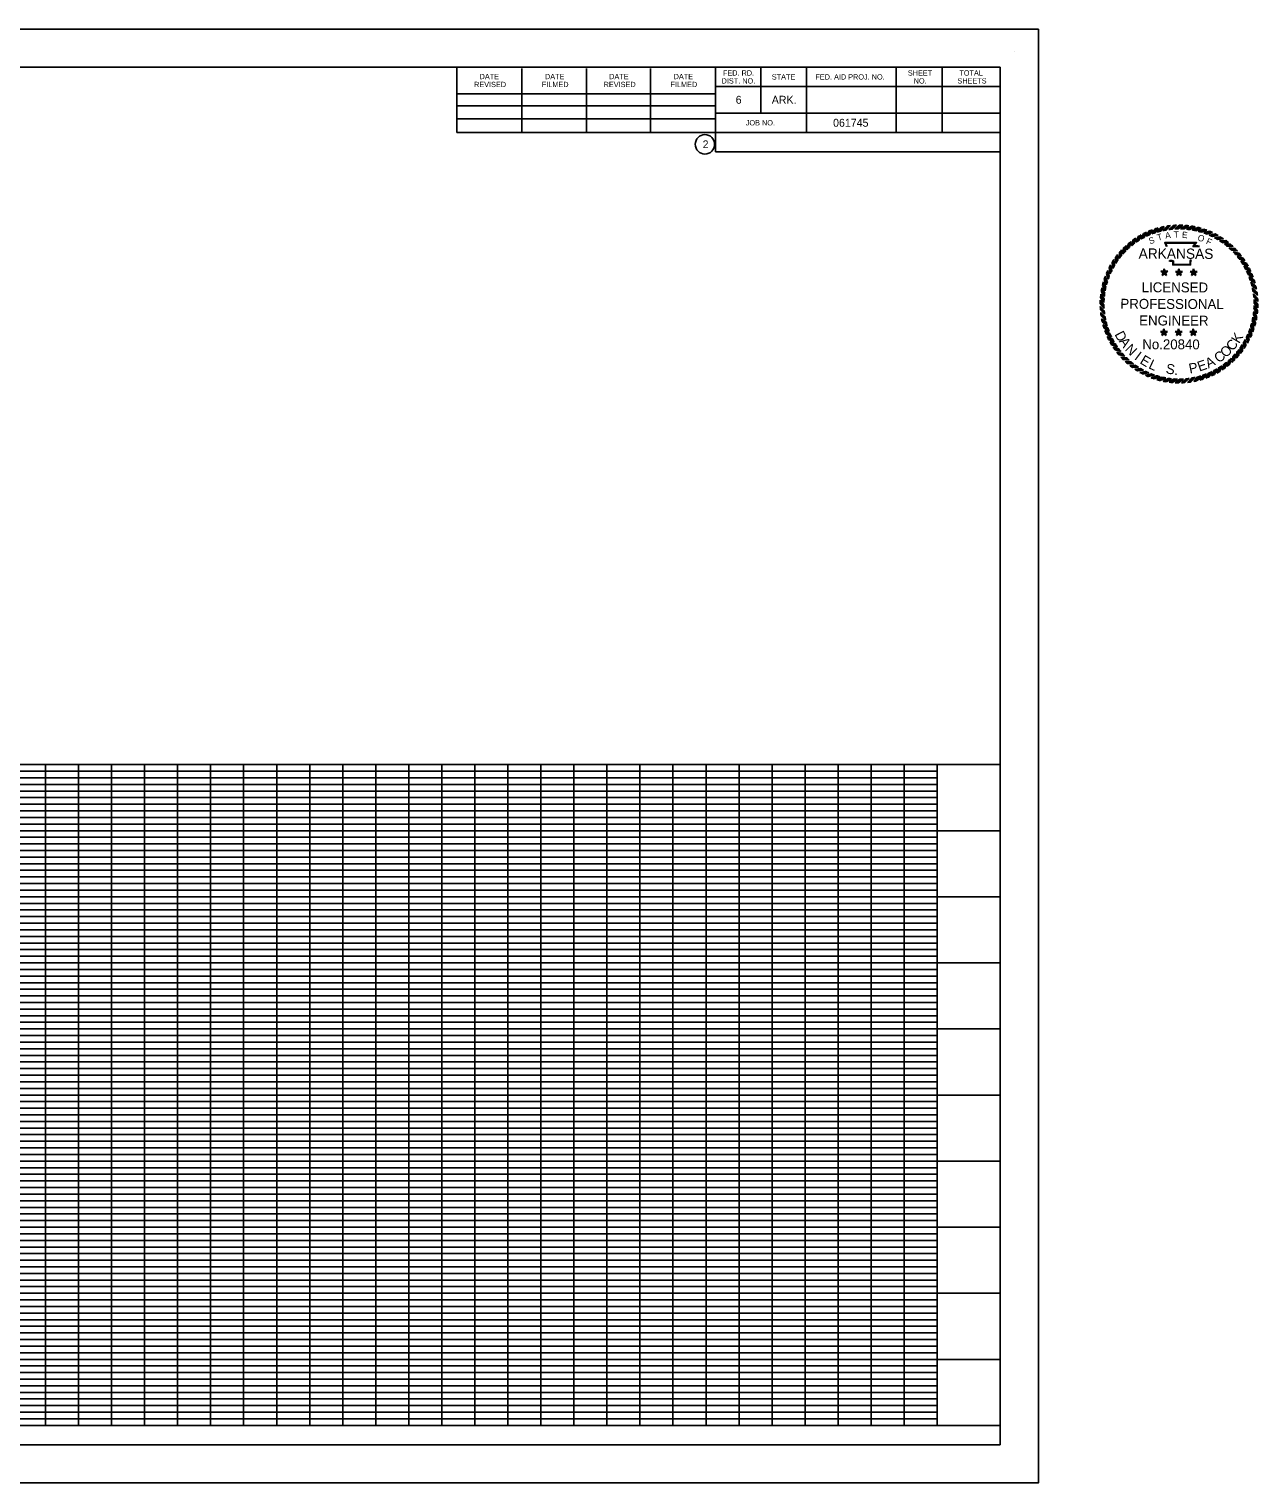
# Model space of a CAD drawing. Extents: x 759422 to 1467355, y 1662254 to 1691786.
# Drawn here: x 1466424 to 1467355, y 1690686 to 1691786 of the extents above; entities that cross this region are included whole.
import ezdxf

# ---------------------------------------------------------------- set-up
doc = ezdxf.new("R2010")
doc.units = 0
doc.layers.add('1', color=7, linetype='Continuous')
doc.layers.add('Default', color=7, linetype='Continuous')

# ---------------------------------------------------------------- blocks, each defined once
blk = doc.blocks.new('STAR')
at = {"layer": 'Default'}
for p, q in [((0.059, 0.019), (-0.059, 0.019)), ((-0.059, 0.019), (0.036, -0.05)), ((0, 0.062), (-0.037, -0.05)), ((-0.036, -0.05), (0.059, 0.019)), ((-0.008, 0), (0.009, 0)), ((0.036, -0.05), (0, 0.062)), ((0, 0.006), (0, -0.008))]:
    blk.add_line(p, q, dxfattribs=at)
blk = doc.blocks.new('RP')
at = {"layer": 'Default'}
for p, q in [((-0.078, 1.266), (0.003, 1.33)), ((-0.058, 1.267), (0.022, 1.33)), ((-0.038, 1.267), (0.04, 1.329)), ((-0.018, 1.268), (0.059, 1.329))]:
    blk.add_line(p, q, dxfattribs=at)
for radius, start, end in [(1.268, 90.7933, 93.5307), (1.33, 87.4562, 89.8699)]:
    blk.add_arc((0, 0), radius, start, end, dxfattribs=at)

msp = doc.modelspace()

# ---------------------------------------------------------------- linework, layer by layer
at = {"layer": '1'}
for p, q in [((1467170.4, 1691768.9), (1467170.4, 1691768.9)), ((1465564.1, 1691757.4), (1467159.4, 1691757.4)), ((1465578.5, 1691757.4), (1466894.6, 1691757.4)), ((1466748.1, 1691708), (1466748.1, 1691757.4)), ((1466797.4, 1691708), (1466797.4, 1691756.4)), ((1466846.2, 1691708), (1466846.2, 1691756.4)), ((1466894.6, 1691708), (1466894.6, 1691756.4)), ((1466943.9, 1691757.4), (1466943.9, 1691693.4)), ((1466978.1, 1691757.4), (1466978.1, 1691722.7)), ((1467012.8, 1691757.4), (1467012.8, 1691708)), ((1467080.7, 1691757.4), (1467080.7, 1691708)), ((1467115.4, 1691757.4), (1467115.4, 1691708)), ((1467159.4, 1690715), (1467159.4, 1691757.4)), ((1466748.1, 1691737.3), (1466943.9, 1691737.3)), ((1467159.4, 1691742.7), (1466943.9, 1691742.7)), ((1467159.4, 1691742.8), (1467159.4, 1691742.8)), ((1466748.1, 1691728), (1466943.9, 1691728)), ((1466748.1, 1691708), (1466748.1, 1691718.3)), ((1466748.1, 1691718.3), (1466943.9, 1691718.3)), ((1467159.4, 1691722.7), (1466943.9, 1691722.7)), ((1466958.7, 1691722.7), (1467159.4, 1691722.7)), ((1467159.4, 1691708), (1466748.1, 1691708)), ((1466943.9, 1691693.4), (1467159.4, 1691693.4)), ((1467159.4, 1691229.7), (1465564.1, 1691229.7)), ((1466436.7, 1690729.7), (1466436.7, 1691229.7)), ((1466461.7, 1690729.7), (1466461.7, 1691229.7)), ((1466486.7, 1690729.7), (1466486.7, 1691229.7)), ((1466511.7, 1690729.7), (1466511.7, 1691229.7)), ((1466536.7, 1690729.7), (1466536.7, 1691229.7)), ((1466561.7, 1690729.7), (1466561.7, 1691229.7)), ((1466586.7, 1690729.7), (1466586.7, 1691229.7)), ((1466611.7, 1690729.7), (1466611.7, 1691229.7)), ((1466636.7, 1690729.7), (1466636.7, 1691229.7)), ((1466661.7, 1690729.7), (1466661.7, 1691229.7)), ((1466686.7, 1690729.7), (1466686.7, 1691229.7)), ((1466711.7, 1690729.7), (1466711.7, 1691229.7)), ((1466736.7, 1690729.7), (1466736.7, 1691229.7)), ((1466761.7, 1690729.7), (1466761.7, 1691229.7)), ((1466786.7, 1690729.7), (1466786.7, 1691229.7)), ((1466811.7, 1690729.7), (1466811.7, 1691229.7)), ((1466836.7, 1690729.7), (1466836.7, 1691229.7)), ((1466861.7, 1690729.7), (1466861.7, 1691229.7)), ((1466886.7, 1690729.7), (1466886.7, 1691229.7)), ((1466911.7, 1690729.7), (1466911.7, 1691229.7)), ((1466936.7, 1690729.7), (1466936.7, 1691229.7)), ((1466961.7, 1690729.7), (1466961.7, 1691229.7)), ((1466986.7, 1690729.7), (1466986.7, 1691229.7)), ((1467011.7, 1690729.7), (1467011.7, 1691229.7)), ((1467036.7, 1690729.7), (1467036.7, 1691229.7)), ((1467061.7, 1690729.7), (1467061.7, 1691229.7)), ((1467086.7, 1690729.7), (1467086.7, 1691229.7)), ((1467111.7, 1690729.7), (1467111.7, 1691229.7)), ((1467111.7, 1691224.7), (1465611.7, 1691224.7)), ((1467111.7, 1691219.7), (1465611.7, 1691219.7)), ((1467111.7, 1691214.7), (1465611.7, 1691214.7)), ((1467111.7, 1691209.7), (1465611.7, 1691209.7)), ((1467111.7, 1691204.7), (1465611.7, 1691204.7)), ((1467111.7, 1691199.7), (1465611.7, 1691199.7)), ((1467111.7, 1691194.7), (1465611.7, 1691194.7)), ((1467111.7, 1691189.7), (1465611.7, 1691189.7)), ((1467111.7, 1691184.7), (1465611.7, 1691184.7)), ((1467159.4, 1691179.7), (1465564.1, 1691179.7)), ((1467111.7, 1691174.7), (1465611.7, 1691174.7)), ((1467111.7, 1691169.7), (1465611.7, 1691169.7)), ((1467111.7, 1691164.7), (1465611.7, 1691164.7)), ((1467111.7, 1691159.7), (1465611.7, 1691159.7)), ((1467111.7, 1691154.7), (1465611.7, 1691154.7)), ((1467111.7, 1691149.7), (1465611.7, 1691149.7)), ((1467111.7, 1691144.7), (1465611.7, 1691144.7)), ((1467159.4, 1691129.7), (1465564.1, 1691129.7)), ((1467111.7, 1691139.7), (1465611.7, 1691139.7)), ((1467111.7, 1691134.7), (1465611.7, 1691134.7)), ((1467111.7, 1691124.7), (1465611.7, 1691124.7)), ((1467111.7, 1691119.7), (1465611.7, 1691119.7)), ((1467111.7, 1691114.7), (1465611.7, 1691114.7)), ((1467111.7, 1691109.7), (1465611.7, 1691109.7)), ((1467111.7, 1691104.7), (1465611.7, 1691104.7)), ((1467111.7, 1691099.7), (1465611.7, 1691099.7)), ((1467111.7, 1691094.7), (1465611.7, 1691094.7)), ((1467111.7, 1691089.7), (1465611.7, 1691089.7)), ((1467159.4, 1691079.7), (1465564.1, 1691079.7)), ((1467111.7, 1691084.7), (1465611.7, 1691084.7)), ((1467111.7, 1691074.7), (1465611.7, 1691074.7)), ((1467111.7, 1691069.7), (1465611.7, 1691069.7)), ((1467111.7, 1691064.7), (1465611.7, 1691064.7)), ((1467111.7, 1691059.7), (1465611.7, 1691059.7)), ((1467111.7, 1691054.7), (1465611.7, 1691054.7)), ((1467111.7, 1691049.7), (1465611.7, 1691049.7)), ((1467111.7, 1691044.7), (1465611.7, 1691044.7)), ((1467111.7, 1691039.7), (1465611.7, 1691039.7)), ((1467111.7, 1691034.7), (1465611.7, 1691034.7)), ((1467159.4, 1691029.7), (1465564.1, 1691029.7)), ((1467111.7, 1691024.7), (1465611.7, 1691024.7)), ((1467111.7, 1691019.7), (1465611.7, 1691019.7)), ((1467111.7, 1691014.7), (1465611.7, 1691014.7)), ((1467111.7, 1691009.7), (1465611.7, 1691009.7)), ((1467111.7, 1691004.7), (1465611.7, 1691004.7)), ((1467111.7, 1690999.7), (1465611.7, 1690999.7)), ((1467111.7, 1690994.7), (1465611.7, 1690994.7)), ((1467111.7, 1690989.7), (1465611.7, 1690989.7)), ((1467159.4, 1690979.7), (1465564.1, 1690979.7)), ((1467111.7, 1690984.7), (1465611.7, 1690984.7)), ((1467111.7, 1690974.7), (1465611.7, 1690974.7)), ((1467111.7, 1690969.7), (1465611.7, 1690969.7)), ((1467111.7, 1690964.7), (1465611.7, 1690964.7)), ((1467111.7, 1690959.7), (1465611.7, 1690959.7)), ((1467111.7, 1690954.7), (1465611.7, 1690954.7)), ((1467111.7, 1690949.7), (1465611.7, 1690949.7)), ((1467111.7, 1690944.7), (1465611.7, 1690944.7)), ((1467111.7, 1690939.7), (1465611.7, 1690939.7)), ((1467111.7, 1690934.7), (1465611.7, 1690934.7)), ((1467159.4, 1690929.7), (1465564.1, 1690929.7)), ((1467111.7, 1690924.7), (1465611.7, 1690924.7)), ((1467111.7, 1690919.7), (1465611.7, 1690919.7)), ((1467111.7, 1690914.7), (1465611.7, 1690914.7)), ((1467111.7, 1690909.7), (1465611.7, 1690909.7)), ((1467111.7, 1690904.7), (1465611.7, 1690904.7)), ((1467111.7, 1690899.7), (1465611.7, 1690899.7)), ((1467111.7, 1690894.7), (1465611.7, 1690894.7)), ((1467111.7, 1690889.7), (1465611.7, 1690889.7)), ((1467159.4, 1690879.7), (1465564.1, 1690879.7)), ((1467111.7, 1690884.7), (1465611.7, 1690884.7)), ((1467111.7, 1690874.7), (1465611.7, 1690874.7)), ((1467111.7, 1690869.7), (1465611.7, 1690869.7)), ((1467111.7, 1690864.7), (1465611.7, 1690864.7)), ((1467111.7, 1690859.7), (1465611.7, 1690859.7)), ((1467111.7, 1690854.7), (1465611.7, 1690854.7)), ((1467111.7, 1690849.7), (1465611.7, 1690849.7)), ((1467111.7, 1690844.7), (1465611.7, 1690844.7)), ((1467111.7, 1690839.7), (1465611.7, 1690839.7)), ((1467111.7, 1690834.7), (1465611.7, 1690834.7)), ((1467159.4, 1690829.7), (1465564.1, 1690829.7)), ((1467111.7, 1690824.7), (1465611.7, 1690824.7)), ((1467111.7, 1690819.7), (1465611.7, 1690819.7)), ((1467111.7, 1690814.7), (1465611.7, 1690814.7)), ((1467111.7, 1690809.7), (1465611.7, 1690809.7)), ((1467111.7, 1690804.7), (1465611.7, 1690804.7)), ((1467111.7, 1690799.7), (1465611.7, 1690799.7)), ((1467111.7, 1690794.7), (1465611.7, 1690794.7)), ((1467111.7, 1690789.7), (1465611.7, 1690789.7)), ((1467159.4, 1690779.7), (1465564.1, 1690779.7)), ((1467111.7, 1690784.7), (1465611.7, 1690784.7)), ((1467111.7, 1690774.7), (1465611.7, 1690774.7)), ((1467111.7, 1690769.7), (1465611.7, 1690769.7)), ((1467111.7, 1690764.7), (1465611.7, 1690764.7)), ((1467111.7, 1690759.7), (1465611.7, 1690759.7)), ((1467111.7, 1690754.7), (1465611.7, 1690754.7)), ((1467111.7, 1690749.7), (1465611.7, 1690749.7)), ((1467111.7, 1690744.7), (1465611.7, 1690744.7)), ((1467111.7, 1690739.7), (1465611.7, 1690739.7)), ((1467111.7, 1690734.7), (1465611.7, 1690734.7)), ((1467159.4, 1690729.7), (1465564.1, 1690729.7)), ((1467159.4, 1690715), (1465564.1, 1690715))]:
    msp.add_line(p, q, dxfattribs=at)
for points in [[(1467188.3, 1691786.2), (1465488.3, 1691786.2), (1465488.3, 1690686.2), (1467188.3, 1690686.2)], [(1465564.1, 1691229.7), (1465564.1, 1691757.4), (1466748.1, 1691757.4), (1466748.1, 1691708), (1466943.9, 1691708), (1466943.9, 1691693.4), (1467159.4, 1691693.4), (1467159.4, 1691229.7)], [(1465564.1, 1691757.4), (1466748.1, 1691757.4), (1466748.1, 1691708), (1466943.9, 1691708), (1466943.9, 1691693.4), (1467159.4, 1691693.4), (1467159.4, 1691229.7), (1465564.1, 1691229.7)], [(1465611.7, 1691229.7), (1467111.7, 1691229.7), (1467111.7, 1690729.7), (1465611.7, 1690729.7)], [(1465611.7, 1691229.7), (1467111.7, 1691229.7), (1467111.7, 1690729.7), (1465611.7, 1690729.7)]]:
    msp.add_lwpolyline(points, close=True, dxfattribs=at)
msp.add_circle((1466935.9, 1691699), 7.33, dxfattribs=at)
at = {"layer": 'Default'}
for points in [[(1467285.3, 1691621.6), (1467284, 1691624.7), (1467308.1, 1691624.6), (1467306.1, 1691622.1), (1467307.7, 1691622.1), (1467309.1, 1691622.1), (1467310.4, 1691621.9)], [(1467285.7, 1691621.8), (1467284.6, 1691624.3), (1467307.3, 1691624.2), (1467305.3, 1691621.7), (1467307.7, 1691621.7), (1467309.1, 1691621.7), (1467310.4, 1691621.6)], [(1467304.2, 1691611.5), (1467303.8, 1691611.1), (1467303.7, 1691610.6), (1467303.6, 1691609.4), (1467303.5, 1691607.7), (1467290.1, 1691607.8), (1467290.1, 1691610), (1467290.1, 1691610.5), (1467289.5, 1691610.7), (1467287.6, 1691610.7), (1467287.3, 1691611.2)], [(1467304, 1691611.8), (1467303.5, 1691611.4), (1467303.3, 1691610.7), (1467303.2, 1691609.4), (1467303.2, 1691608.1), (1467290.5, 1691608.1), (1467290.5, 1691610), (1467290.5, 1691610.8), (1467289.6, 1691611.1), (1467287.8, 1691611.1), (1467287.6, 1691611.4)]]:
    msp.add_lwpolyline(points, dxfattribs=at)

# ---------------------------------------------------------------- block references
for name, p, xscale, yscale, rotation in [('RP', (1467294.8, 1691578.2), 44.855502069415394, 44.85550206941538, 17.80419999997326), ('RP', (1467294.8, 1691578.2), 44.855502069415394, 44.85550206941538, 13.304199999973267), ('RP', (1467294.8, 1691578.2), 44.855502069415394, 44.855502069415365, 8.804199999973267), ('RP', (1467294.8, 1691578.2), 44.85550206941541, 44.85550206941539, 4.304199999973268), ('RP', (1467294.8, 1691578.2), 44.8555020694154, 44.85550206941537, -0.19580000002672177), ('RP', (1467294.8, 1691578.2), 44.8555020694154, 44.85550206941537, -4.695800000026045), ('RP', (1467294.8, 1691578.2), 44.85550206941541, 44.85550206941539, -9.195800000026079), ('RP', (1467294.8, 1691578.2), 44.855502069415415, 44.85550206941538, -13.695800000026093), ('RP', (1467294.8, 1691578.2), 44.85550206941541, 44.85550206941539, -18.195800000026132), ('RP', (1467294.8, 1691578.2), 44.85550206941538, 44.85550206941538, 40.304199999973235), ('RP', (1467294.8, 1691578.2), 44.85550206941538, 44.85550206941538, 35.80419999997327), ('RP', (1467294.8, 1691578.2), 44.85550206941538, 44.85550206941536, 31.30419999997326), ('RP', (1467294.8, 1691578.2), 44.855502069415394, 44.855502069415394, 26.804199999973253), ('RP', (1467294.8, 1691578.2), 44.85550206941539, 44.85550206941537, 22.30419999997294), ('RP', (1467294.8, 1691578.2), 44.8555020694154, 44.85550206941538, -22.69580000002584), ('RP', (1467294.8, 1691578.2), 44.855502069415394, 44.85550206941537, -27.19580000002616), ('RP', (1467294.8, 1691578.2), 44.85550206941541, 44.8555020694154, -31.695800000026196), ('RP', (1467294.8, 1691578.2), 44.8555020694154, 44.855502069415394, -36.195800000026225), ('RP', (1467294.8, 1691578.2), 44.85550206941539, 44.8555020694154, -40.69580000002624), ('RP', (1467294.8, 1691578.2), 44.8555020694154, 44.85550206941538, 53.804199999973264), ('RP', (1467294.8, 1691578.2), 44.8555020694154, 44.8555020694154, 49.304199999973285), ('RP', (1467294.8, 1691578.2), 44.85550206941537, 44.855502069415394, 44.80419999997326), ('RP', (1467294.8, 1691578.2), 44.85550206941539, 44.85550206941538, -45.195800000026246), ('RP', (1467294.8, 1691578.2), 44.85550206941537, 44.85550206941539, -49.695800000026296), ('RP', (1467294.8, 1691578.2), 44.85550206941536, 44.855502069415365, -54.1958000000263), ('RP', (1467294.8, 1691578.2), 44.85550206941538, 44.8555020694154, 67.30419999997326), ('RP', (1467294.8, 1691578.2), 44.85550206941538, 44.855502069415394, 62.804199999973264), ('RP', (1467294.8, 1691578.2), 44.85550206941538, 44.85550206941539, 58.304199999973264), ('STAR', (1467283.6, 1691602.1), 44.8555020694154, 44.85550206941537, -0.19580000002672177), ('STAR', (1467294.7, 1691602), 44.8555020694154, 44.85550206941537, -0.19580000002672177), ('STAR', (1467305.8, 1691602), 44.8555020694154, 44.85550206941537, -0.19580000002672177), ('RP', (1467294.8, 1691578.2), 44.85550206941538, 44.85550206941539, -58.695800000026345), ('RP', (1467294.8, 1691578.2), 44.85550206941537, 44.85550206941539, -63.19580000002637), ('RP', (1467294.8, 1691578.2), 44.85550206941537, 44.85550206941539, -67.6958000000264), ('RP', (1467294.8, 1691578.2), 44.85550206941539, 44.85550206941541, 76.30419999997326), ('RP', (1467294.8, 1691578.2), 44.85550206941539, 44.855502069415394, 71.80419999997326), ('RP', (1467294.8, 1691578.2), 44.85550206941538, 44.8555020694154, -72.19580000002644), ('RP', (1467294.8, 1691578.2), 44.85550206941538, 44.85550206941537, -76.69580000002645), ('RP', (1467294.8, 1691578.2), 44.855502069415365, 44.85550206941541, 85.30419999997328), ('RP', (1467294.8, 1691578.2), 44.85550206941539, 44.85550206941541, 89.80419999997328), ('RP', (1467294.8, 1691578.2), 44.85550206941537, 44.8555020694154, 80.80419999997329), ('RP', (1467294.8, 1691578.2), 44.85550206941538, 44.8555020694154, -81.19580000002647), ('RP', (1467294.8, 1691578.2), 44.85550206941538, 44.855502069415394, -85.69580000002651), ('RP', (1467294.8, 1691578.2), 44.85550206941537, 44.8555020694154, -90.19580000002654), ('RP', (1467294.8, 1691578.2), 44.85550206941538, 44.85550206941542, 94.30419999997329), ('RP', (1467294.8, 1691578.2), 44.85550206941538, 44.855502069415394, 98.8041999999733), ('RP', (1467294.8, 1691578.2), 44.85550206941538, 44.855502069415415, -99.19580000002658), ('RP', (1467294.8, 1691578.2), 44.85550206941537, 44.85550206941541, -94.69580000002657), ('RP', (1467294.8, 1691578.2), 44.85550206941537, 44.8555020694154, 103.30419999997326), ('RP', (1467294.8, 1691578.2), 44.85550206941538, 44.855502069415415, 107.80419999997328), ('RP', (1467294.8, 1691578.2), 44.85550206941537, 44.85550206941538, 112.3041999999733), ('STAR', (1467283.4, 1691556.6), 44.8555020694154, 44.85550206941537, -0.19580000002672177), ('STAR', (1467294.5, 1691556.5), 44.8555020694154, 44.85550206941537, -0.19580000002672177), ('STAR', (1467305.6, 1691556.5), 44.8555020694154, 44.85550206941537, -0.19580000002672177), ('RP', (1467294.8, 1691578.2), 44.85550206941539, 44.855502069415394, -112.69580000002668), ('RP', (1467294.8, 1691578.2), 44.85550206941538, 44.85550206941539, -108.19580000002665), ('RP', (1467294.8, 1691578.2), 44.85550206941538, 44.8555020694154, -103.69580000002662), ('RP', (1467294.8, 1691578.2), 44.85550206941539, 44.8555020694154, 116.80419999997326), ('RP', (1467294.8, 1691578.2), 44.855502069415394, 44.85550206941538, 121.30419999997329), ('RP', (1467294.8, 1691578.2), 44.85550206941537, 44.85550206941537, 125.80419999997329), ('RP', (1467294.8, 1691578.2), 44.8555020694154, 44.8555020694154, -126.19580000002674), ('RP', (1467294.8, 1691578.2), 44.85550206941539, 44.8555020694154, -121.69580000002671), ('RP', (1467294.8, 1691578.2), 44.85550206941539, 44.85550206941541, -117.19580000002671), ('RP', (1467294.8, 1691578.2), 44.85550206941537, 44.85550206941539, 130.3041999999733), ('RP', (1467294.8, 1691578.2), 44.855502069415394, 44.85550206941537, 134.80419999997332), ('RP', (1467294.8, 1691578.2), 44.85550206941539, 44.85550206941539, 139.30419999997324), ('RP', (1467294.8, 1691578.2), 44.85550206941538, 44.85550206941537, -139.69580000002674), ('RP', (1467294.8, 1691578.2), 44.85550206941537, 44.855502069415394, -135.19580000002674), ('RP', (1467294.8, 1691578.2), 44.85550206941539, 44.85550206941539, -130.6958000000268), ('RP', (1467294.8, 1691578.2), 44.85550206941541, 44.855502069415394, 143.8041999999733), ('RP', (1467294.8, 1691578.2), 44.85550206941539, 44.85550206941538, 148.3041999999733), ('RP', (1467294.8, 1691578.2), 44.8555020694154, 44.855502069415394, 152.8041999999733), ('RP', (1467294.8, 1691578.2), 44.8555020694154, 44.85550206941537, 157.3041999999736), ('RP', (1467294.8, 1691578.2), 44.85550206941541, 44.85550206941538, 161.80419999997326), ('RP', (1467294.8, 1691578.2), 44.855502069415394, 44.85550206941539, -162.19580000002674), ('RP', (1467294.8, 1691578.2), 44.8555020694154, 44.85550206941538, -157.6958000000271), ('RP', (1467294.8, 1691578.2), 44.85550206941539, 44.85550206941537, -153.1958000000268), ('RP', (1467294.8, 1691578.2), 44.85550206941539, 44.85550206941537, -148.69580000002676), ('RP', (1467294.8, 1691578.2), 44.85550206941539, 44.855502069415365, -144.19580000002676), ('RP', (1467294.8, 1691578.2), 44.855502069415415, 44.85550206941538, 166.3041999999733), ('RP', (1467294.8, 1691578.2), 44.8555020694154, 44.855502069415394, 170.8041999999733), ('RP', (1467294.8, 1691578.2), 44.8555020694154, 44.85550206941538, 175.3041999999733), ('RP', (1467294.8, 1691578.2), 44.85550206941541, 44.85550206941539, 179.8041999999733), ('RP', (1467294.8, 1691578.2), 44.8555020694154, 44.85550206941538, -175.69580000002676), ('RP', (1467294.8, 1691578.2), 44.85550206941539, 44.85550206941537, -171.19580000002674), ('RP', (1467294.8, 1691578.2), 44.855502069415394, 44.85550206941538, -166.69580000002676)]:
    msp.add_blockref(name, p, dxfattribs=dict(at, xscale=xscale, yscale=yscale, rotation=rotation))

# ---------------------------------------------------------------- texts
at = {"layer": '1'}
for s, height, p in [('REVISED', 4, (1466761.1, 1691742.3)), ('DATE', 4, (1466765.3, 1691748.3)), ('FILMED', 4, (1466812.4, 1691742.3)), ('DATE', 4, (1466814.8, 1691748.3)), ('REVISED', 4, (1466859.2, 1691742.3)), ('DATE', 4, (1466863.4, 1691748.3)), ('FILMED', 4, (1466909.8, 1691742.3)), ('DATE', 4, (1466912.2, 1691748.3)), ('DIST. NO.', 4, (1466948.5, 1691745)), ('FED. RD.', 4, (1466949.5, 1691751)), ('STATE', 4, (1466986.5, 1691748)), ('FED. AID PROJ. NO.', 4, (1467019.5, 1691748)), ('SHEET', 4, (1467089.5, 1691751)), ('NO.', 4, (1467093.9, 1691745)), ('SHEETS', 4, (1467127, 1691745)), ('TOTAL', 4, (1467128.5, 1691751)), ('6', 6, (1466959.2, 1691729.7)), ('ARK.', 6, (1466986.5, 1691729.7)), ('JOB NO.', 4, (1466966.8, 1691713.3)), ('061745', 6, (1467032.9, 1691712.3)), ('2', 5.86, (1466934.2, 1691696.1))]:
    msp.add_text(s, height=height, dxfattribs=at).set_placement(p)
at = {"layer": 'Default'}
for s, height, rotation, p in [('S', 4.76, 19.5768, (1467272.8, 1691623.3)), ('T', 4.76, 16.7057, (1467278.9, 1691626)), ('A', 4.76, 8.483, (1467284.6, 1691627.5)), ('T', 4.76, 1.2831, (1467290.8, 1691628.4)), ('E', 4.76, 356.4762, (1467296.9, 1691628.2)), ('O', 4.76, 341.026, (1467308.4, 1691626.5)), ('F', 4.76, 335.167, (1467314.8, 1691624)), ('ARKANSAS', 7.77, 359.8042, (1467264.2, 1691612.5)), ('LICENSED', 7.52, 359.8042, (1467266.5, 1691587.1)), ('PROFESSIONAL', 7.52, 359.8042, (1467250.4, 1691574.6)), ('ENGINEER', 7.52, 359.8042, (1467264.6, 1691562)), ('D', 7.52, 297.6938, (1467245.8, 1691555.3)), ('A', 7.52, 304.6023, (1467249, 1691549.9)), ('N', 7.52, 315.1572, (1467253.4, 1691543.5)), ('No.20840', 7.49, 359.8042, (1467267, 1691544)), ('C', 7.52, 51.6469, (1467335.5, 1691542.1)), ('K', 7.52, 59.4479, (1467340.3, 1691547.8)), ('I', 7.52, 323.3542, (1467260.5, 1691536.7)), ('E', 7.52, 328.9329, (1467264.6, 1691533.6)), ('L', 7.52, 335.0568, (1467271.2, 1691529.8)), ('E', 7.52, 19.051, (1467310.2, 1691527)), ('A', 7.52, 27.2121, (1467317, 1691529.3)), ('C', 7.52, 36.5748, (1467324.8, 1691533.2)), ('O', 7.52, 43.9981, (1467330.2, 1691537.1)), ('S.', 7.52, 350.5565, (1467284.4, 1691525.8)), ('P', 7.52, 11.2447, (1467303, 1691525.5))]:
    msp.add_text(s, height=height, rotation=rotation, dxfattribs=at).set_placement(p)

doc.saveas('drawing.dxf')
